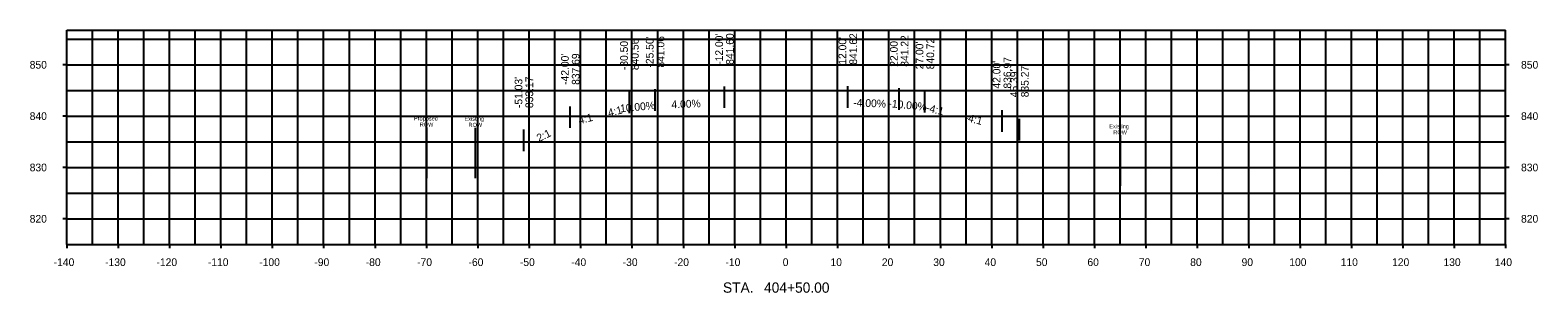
# Model space of a CAD drawing. Extents: x -147 to 146, y 806 to 857.
import ezdxf

# ---------------------------------------------------------------- set-up
doc = ezdxf.new("R2010")
doc.units = 0
for name, color, linetype in [('Default', 7, 'Continuous'), ('rowdsnLineTE', 7, 'Continuous'), ('rowdsnParcelML', 7, 'Continuous'), ('rowdsnParcelSR', 7, 'Continuous'), ('rowdsnPSConstructPlot', 7, 'Continuous'), ('rowdsnShapeTE', 7, 'Continuous')]:
    doc.layers.add(name, color=color, linetype=linetype)

msp = doc.modelspace()

# ---------------------------------------------------------------- linework, layer by layer
at = {"layer": 'rowdsnLineTE'}
for p, q in [((-25.5, 841.06), (-25.5, 845.26)), ((-25.5, 841.06), (-25.5, 845.26)), ((-12, 841.6), (-12, 845.8)), ((-12, 841.6), (-12, 845.8)), ((12, 841.62), (12, 845.82)), ((12, 841.62), (12, 845.82)), ((22, 841.22), (22, 845.42)), ((-30.5, 840.56), (-30.5, 844.76)), ((-30.5, 840.56), (-30.5, 844.76)), ((27, 840.72), (27, 844.92)), ((27, 840.72), (27, 844.92)), ((-42, 837.69), (-42, 841.89)), ((42, 836.97), (42, 841.17)), ((45.39, 835.27), (45.39, 839.47)), ((45.39, 835.27), (45.39, 839.47)), ((-51.03, 833.17), (-51.03, 837.37)), ((-51.03, 833.17), (-51.03, 837.37))]:
    msp.add_line(p, q, dxfattribs=at)
at = {"layer": 'rowdsnParcelML'}
for p, q in [((-130, 815), (-130, 856.75)), ((-130, 815), (-130, 856.75)), ((-120, 815), (-120, 856.75)), ((-120, 815), (-120, 856.75)), ((-110, 815), (-110, 856.75)), ((-110, 815), (-110, 856.75)), ((-100, 815), (-100, 856.75)), ((-100, 815), (-100, 856.75)), ((-90, 815), (-90, 856.75)), ((-90, 815), (-90, 856.75)), ((-80, 815), (-80, 856.75)), ((-80, 815), (-80, 856.75)), ((-70, 815), (-70, 856.75)), ((-70, 815), (-70, 856.75)), ((-60, 815), (-60, 856.75)), ((-60, 815), (-60, 856.75)), ((-50, 815), (-50, 856.75)), ((-50, 815), (-50, 856.75)), ((-40, 815), (-40, 856.75)), ((-40, 815), (-40, 856.75)), ((-30, 815), (-30, 856.75)), ((-30, 815), (-30, 856.75)), ((-20, 815), (-20, 856.75)), ((-20, 815), (-20, 856.75)), ((-10, 815), (-10, 856.75)), ((-10, 815), (-10, 856.75)), ((0, 815), (0, 856.75)), ((0, 815), (0, 856.75)), ((10, 815), (10, 856.75)), ((10, 815), (10, 856.75)), ((20, 815), (20, 856.75)), ((20, 815), (20, 856.75)), ((30, 815), (30, 856.75)), ((30, 815), (30, 856.75)), ((40, 815), (40, 856.75)), ((40, 815), (40, 856.75)), ((50, 815), (50, 856.75)), ((50, 815), (50, 856.75)), ((60, 815), (60, 856.75)), ((60, 815), (60, 856.75)), ((70, 815), (70, 856.75)), ((70, 815), (70, 856.75)), ((80, 815), (80, 856.75)), ((80, 815), (80, 856.75)), ((90, 815), (90, 856.75)), ((90, 815), (90, 856.75)), ((100, 815), (100, 856.75)), ((100, 815), (100, 856.75)), ((110, 815), (110, 856.75)), ((110, 815), (110, 856.75)), ((120, 815), (120, 856.75)), ((120, 815), (120, 856.75)), ((130, 815), (130, 856.75)), ((130, 815), (130, 856.75)), ((-140, 850), (-140.72, 850)), ((-140, 850), (-140.72, 850)), ((-140, 850), (140, 850)), ((-140, 850), (140, 850)), ((140.72, 850), (140, 850)), ((140.72, 850), (140, 850)), ((-140, 840), (-140.72, 840)), ((-140, 840), (-140.72, 840)), ((-140, 840), (140, 840)), ((-140, 840), (140, 840)), ((140.72, 840), (140, 840)), ((140.72, 840), (140, 840)), ((-140, 830), (-140.72, 830)), ((-140, 830), (-140.72, 830)), ((-140, 830), (140, 830)), ((-140, 830), (140, 830)), ((140.72, 830), (140, 830)), ((140.72, 830), (140, 830)), ((-140, 820), (-140.72, 820)), ((-140, 820), (-140.72, 820)), ((-140, 820), (140, 820)), ((-140, 820), (140, 820)), ((140.72, 820), (140, 820)), ((140.72, 820), (140, 820)), ((-140, 815), (-140, 814.28)), ((-140, 815), (-140, 814.28)), ((-130, 815), (-130, 814.28)), ((-130, 815), (-130, 814.28)), ((-120, 815), (-120, 814.28)), ((-120, 815), (-120, 814.28)), ((-110, 815), (-110, 814.28)), ((-110, 815), (-110, 814.28)), ((-100, 815), (-100, 814.28)), ((-100, 815), (-100, 814.28)), ((-90, 815), (-90, 814.28)), ((-90, 815), (-90, 814.28)), ((-80, 815), (-80, 814.28)), ((-80, 815), (-80, 814.28)), ((-70, 815), (-70, 814.28)), ((-70, 815), (-70, 814.28)), ((-60, 815), (-60, 814.28)), ((-60, 815), (-60, 814.28)), ((-50, 815), (-50, 814.28)), ((-50, 815), (-50, 814.28)), ((-40, 815), (-40, 814.28)), ((-40, 815), (-40, 814.28)), ((-30, 815), (-30, 814.28)), ((-30, 815), (-30, 814.28)), ((-20, 815), (-20, 814.28)), ((-20, 815), (-20, 814.28)), ((-10, 815), (-10, 814.28)), ((-10, 815), (-10, 814.28)), ((0, 815), (0, 814.28)), ((0, 815), (0, 814.28)), ((10, 815), (10, 814.28)), ((10, 815), (10, 814.28)), ((20, 815), (20, 814.28)), ((20, 815), (20, 814.28)), ((30, 815), (30, 814.28)), ((30, 815), (30, 814.28)), ((40, 815), (40, 814.28)), ((40, 815), (40, 814.28)), ((50, 815), (50, 814.28)), ((50, 815), (50, 814.28)), ((60, 815), (60, 814.28)), ((60, 815), (60, 814.28)), ((70, 815), (70, 814.28)), ((70, 815), (70, 814.28)), ((80, 815), (80, 814.28)), ((80, 815), (80, 814.28)), ((90, 815), (90, 814.28)), ((90, 815), (90, 814.28)), ((100, 815), (100, 814.28)), ((100, 815), (100, 814.28)), ((110, 815), (110, 814.28)), ((110, 815), (110, 814.28)), ((120, 815), (120, 814.28)), ((120, 815), (120, 814.28)), ((130, 815), (130, 814.28)), ((130, 815), (130, 814.28)), ((140, 815), (140, 814.28)), ((140, 815), (140, 814.28))]:
    msp.add_line(p, q, dxfattribs=at)
at = {"layer": 'rowdsnParcelSR'}
for p, q in [((-135, 815), (-135, 856.75)), ((-135, 815), (-135, 856.75)), ((-125, 815), (-125, 856.75)), ((-125, 815), (-125, 856.75)), ((-115, 815), (-115, 856.75)), ((-115, 815), (-115, 856.75)), ((-105, 815), (-105, 856.75)), ((-105, 815), (-105, 856.75)), ((-95, 815), (-95, 856.75)), ((-95, 815), (-95, 856.75)), ((-85, 815), (-85, 856.75)), ((-85, 815), (-85, 856.75)), ((-75, 815), (-75, 856.75)), ((-75, 815), (-75, 856.75)), ((-65, 815), (-65, 856.75)), ((-65, 815), (-65, 856.75)), ((-55, 815), (-55, 856.75)), ((-55, 815), (-55, 856.75)), ((-45, 815), (-45, 856.75)), ((-45, 815), (-45, 856.75)), ((-35, 815), (-35, 856.75)), ((-35, 815), (-35, 856.75)), ((-25, 815), (-25, 856.75)), ((-25, 815), (-25, 856.75)), ((-15, 815), (-15, 856.75)), ((-15, 815), (-15, 856.75)), ((-5, 815), (-5, 856.75)), ((-5, 815), (-5, 856.75)), ((5, 815), (5, 856.75)), ((5, 815), (5, 856.75)), ((15, 815), (15, 856.75)), ((15, 815), (15, 856.75)), ((25, 815), (25, 856.75)), ((25, 815), (25, 856.75)), ((35, 815), (35, 856.75)), ((35, 815), (35, 856.75)), ((45, 815), (45, 856.75)), ((45, 815), (45, 856.75)), ((55, 815), (55, 856.75)), ((55, 815), (55, 856.75)), ((65, 815), (65, 856.75)), ((65, 815), (65, 856.75)), ((75, 815), (75, 856.75)), ((75, 815), (75, 856.75)), ((85, 815), (85, 856.75)), ((85, 815), (85, 856.75)), ((95, 815), (95, 856.75)), ((95, 815), (95, 856.75)), ((105, 815), (105, 856.75)), ((105, 815), (105, 856.75)), ((115, 815), (115, 856.75)), ((115, 815), (115, 856.75)), ((125, 815), (125, 856.75)), ((125, 815), (125, 856.75)), ((135, 815), (135, 856.75)), ((135, 815), (135, 856.75)), ((-140, 855), (140, 855)), ((-140, 855), (140, 855)), ((-140, 845), (140, 845)), ((-140, 845), (140, 845)), ((-140, 835), (140, 835)), ((-140, 835), (140, 835)), ((-140, 825), (140, 825)), ((-140, 825), (140, 825))]:
    msp.add_line(p, q, dxfattribs=at)
at = {"layer": 'rowdsnPSConstructPlot'}
for p, q in [((-140, 856.75), (140, 856.75)), ((-140, 815), (-140, 856.75)), ((-140, 856.75), (140, 856.75)), ((-140, 815), (-140, 856.75)), ((140, 815), (140, 856.75)), ((140, 815), (140, 856.75)), ((-140, 815), (140, 815)), ((-140, 815), (140, 815))]:
    msp.add_line(p, q, dxfattribs=at)
at = {"layer": 'rowdsnShapeTE'}
for p, q in [((-70, 837.77), (-70, 827.92)), ((-60.5, 837.74), (-60.5, 827.9)), ((-60.5, 837.74), (-60.5, 827.9)), ((64.97, 836.28), (64.97, 826.43))]:
    msp.add_line(p, q, dxfattribs=at)

# ---------------------------------------------------------------- texts
at = {"layer": 'Default'}
for s, height, p in [('850', 1.5, (-147.2, 849.25)), ('850', 1.5, (-147.2, 849.25)), ('850', 1.5, (143, 849.25)), ('850', 1.5, (143, 849.25)), ('840', 1.5, (-147.2, 839.25)), ('840', 1.5, (-147.2, 839.25)), ('840', 1.5, (143, 839.25)), ('840', 1.5, (143, 839.25)), ('830', 1.5, (-147.2, 829.25)), ('830', 1.5, (-147.2, 829.25)), ('830', 1.5, (143, 829.25)), ('830', 1.5, (143, 829.25)), ('820', 1.5, (-147.2, 819.25)), ('820', 1.5, (-147.2, 819.25)), ('820', 1.5, (143, 819.25)), ('820', 1.5, (143, 819.25)), ('-140', 1.5, (-142.53, 810.8)), ('-140', 1.5, (-142.53, 810.8)), ('-130', 1.5, (-132.53, 810.8)), ('-130', 1.5, (-132.53, 810.8)), ('-120', 1.5, (-122.53, 810.8)), ('-120', 1.5, (-122.53, 810.8)), ('-110', 1.5, (-112.53, 810.8)), ('-110', 1.5, (-112.53, 810.8)), ('-100', 1.5, (-102.53, 810.8)), ('-100', 1.5, (-102.53, 810.8)), ('-90', 1.5, (-91.81, 810.8)), ('-90', 1.5, (-91.81, 810.8)), ('-80', 1.5, (-81.81, 810.8)), ('-80', 1.5, (-81.81, 810.8)), ('-70', 1.5, (-71.81, 810.8)), ('-70', 1.5, (-71.81, 810.8)), ('-60', 1.5, (-61.81, 810.8)), ('-60', 1.5, (-61.81, 810.8)), ('-50', 1.5, (-51.81, 810.8)), ('-50', 1.5, (-51.81, 810.8)), ('-40', 1.5, (-41.81, 810.8)), ('-40', 1.5, (-41.81, 810.8)), ('-30', 1.5, (-31.81, 810.8)), ('-30', 1.5, (-31.81, 810.8)), ('-20', 1.5, (-21.81, 810.8)), ('-20', 1.5, (-21.81, 810.8)), ('-10', 1.5, (-11.81, 810.8)), ('-10', 1.5, (-11.81, 810.8)), ('0', 1.5, (-0.67, 810.8)), ('0', 1.5, (-0.67, 810.8)), ('10', 1.5, (8.62, 810.8)), ('10', 1.5, (8.62, 810.8)), ('20', 1.5, (18.62, 810.8)), ('20', 1.5, (18.62, 810.8)), ('30', 1.5, (28.62, 810.8)), ('30', 1.5, (28.62, 810.8)), ('40', 1.5, (38.62, 810.8)), ('40', 1.5, (38.62, 810.8)), ('50', 1.5, (48.62, 810.8)), ('50', 1.5, (48.62, 810.8)), ('60', 1.5, (58.62, 810.8)), ('60', 1.5, (58.62, 810.8)), ('70', 1.5, (68.62, 810.8)), ('70', 1.5, (68.62, 810.8)), ('80', 1.5, (78.62, 810.8)), ('80', 1.5, (78.62, 810.8)), ('90', 1.5, (88.62, 810.8)), ('90', 1.5, (88.62, 810.8)), ('100', 1.5, (97.9, 810.8)), ('100', 1.5, (97.9, 810.8)), ('110', 1.5, (107.9, 810.8)), ('110', 1.5, (107.9, 810.8)), ('120', 1.5, (117.9, 810.8)), ('120', 1.5, (117.9, 810.8)), ('130', 1.5, (127.9, 810.8)), ('130', 1.5, (127.9, 810.8)), ('140', 1.5, (137.9, 810.8)), ('140', 1.5, (137.9, 810.8)), ('STA.', 2.004, (-12.3, 805.6)), ('STA.', 2.004, (-12.3, 805.6)), ('404+50.00', 2.004, (-4.31, 805.6)), ('404+50.00', 2.004, (-4.31, 805.6))]:
    msp.add_text(s, height=height, dxfattribs=at).set_placement(p)
at = {"layer": 'rowdsnLineTE'}
for s, rotation, p in [("-30.50'", 90, (-30.8, 848.96)), ("-30.50'", 90, (-30.8, 848.96)), ('840.56', 90, (-28.7, 848.96)), ('840.56', 90, (-28.7, 848.96)), ("-25.50'", 90, (-25.8, 849.46)), ("-25.50'", 90, (-25.8, 849.46)), ('841.06', 90, (-23.7, 849.46)), ('841.06', 90, (-23.7, 849.46)), ("-12.00'", 90, (-12.3, 850)), ("-12.00'", 90, (-12.3, 850)), ('841.60', 90, (-10.2, 850)), ('841.60', 90, (-10.2, 850)), ("12.00'", 90, (11.7, 850.02)), ("12.00'", 90, (11.7, 850.02)), ('841.62', 90, (13.8, 850.02)), ('841.62', 90, (13.8, 850.02)), ("22.00'", 90, (21.7, 849.62)), ('841.22', 90, (23.8, 849.62)), ("27.00'", 90, (26.7, 849.12)), ("27.00'", 90, (26.7, 849.12)), ('840.72', 90, (28.8, 849.12)), ('840.72', 90, (28.8, 849.12)), ("-42.00'", 90, (-42.3, 846.09)), ('837.69', 90, (-40.2, 846.09)), ('836.97', 90, (43.8, 845.37)), ("42.00'", 90, (41.7, 845.37)), ("45.39'", 90, (45.09, 843.67)), ("45.39'", 90, (45.09, 843.67)), ('835.27', 90, (47.19, 843.67)), ('835.27', 90, (47.19, 843.67)), ("-51.03'", 90, (-51.33, 841.57)), ("-51.03'", 90, (-51.33, 841.57)), ('833.17', 90, (-49.23, 841.57)), ('833.17', 90, (-49.23, 841.57)), ('10.00%', 5.7106, (-32.24, 840.72)), ('10.00%', 5.7106, (-32.24, 840.72)), ('4.00%', 2.2906, (-22.29, 841.52)), ('4.00%', 2.2906, (-22.29, 841.52)), ('-4.00%', 357.7094, (13.04, 841.91)), ('-4.00%', 357.7094, (13.04, 841.91)), ('-10.00%', 354.2894, (19.85, 841.77)), ('-10.00%', 354.2894, (19.85, 841.77)), ('-4:1', 345.9638, (27.13, 840.99)), ('-4:1', 345.9638, (27.13, 840.99)), ('4:1', 14.0362, (-40.23, 838.43)), ('4:1', 14.0362, (-40.23, 838.43)), ('4:1', 14.0362, (-34.48, 839.87)), ('4:1', 14.0362, (-34.48, 839.87)), ('-4:1', 345.9638, (34.63, 839.11)), ('-4:1', 345.9638, (34.63, 839.11)), ('2:1', 26.5651, (-48.1, 834.94)), ('2:1', 26.5651, (-48.1, 834.94))]:
    msp.add_text(s, height=1.5, rotation=rotation, dxfattribs=at).set_placement(p)
at = {"layer": 'rowdsnShapeTE'}
for s, p in [('Proposed', (-72.43, 839.15)), ('Existing', (-62.59, 839.09)), ('Existing', (-62.59, 839.09)), ('ROW', (-71.31, 837.97)), ('ROW', (-61.81, 837.91)), ('ROW', (-61.81, 837.91)), ('Existing', (62.88, 837.63)), ('ROW', (63.66, 836.45))]:
    msp.add_text(s, height=0.787, dxfattribs=at).set_placement(p)

doc.saveas('drawing.dxf')
